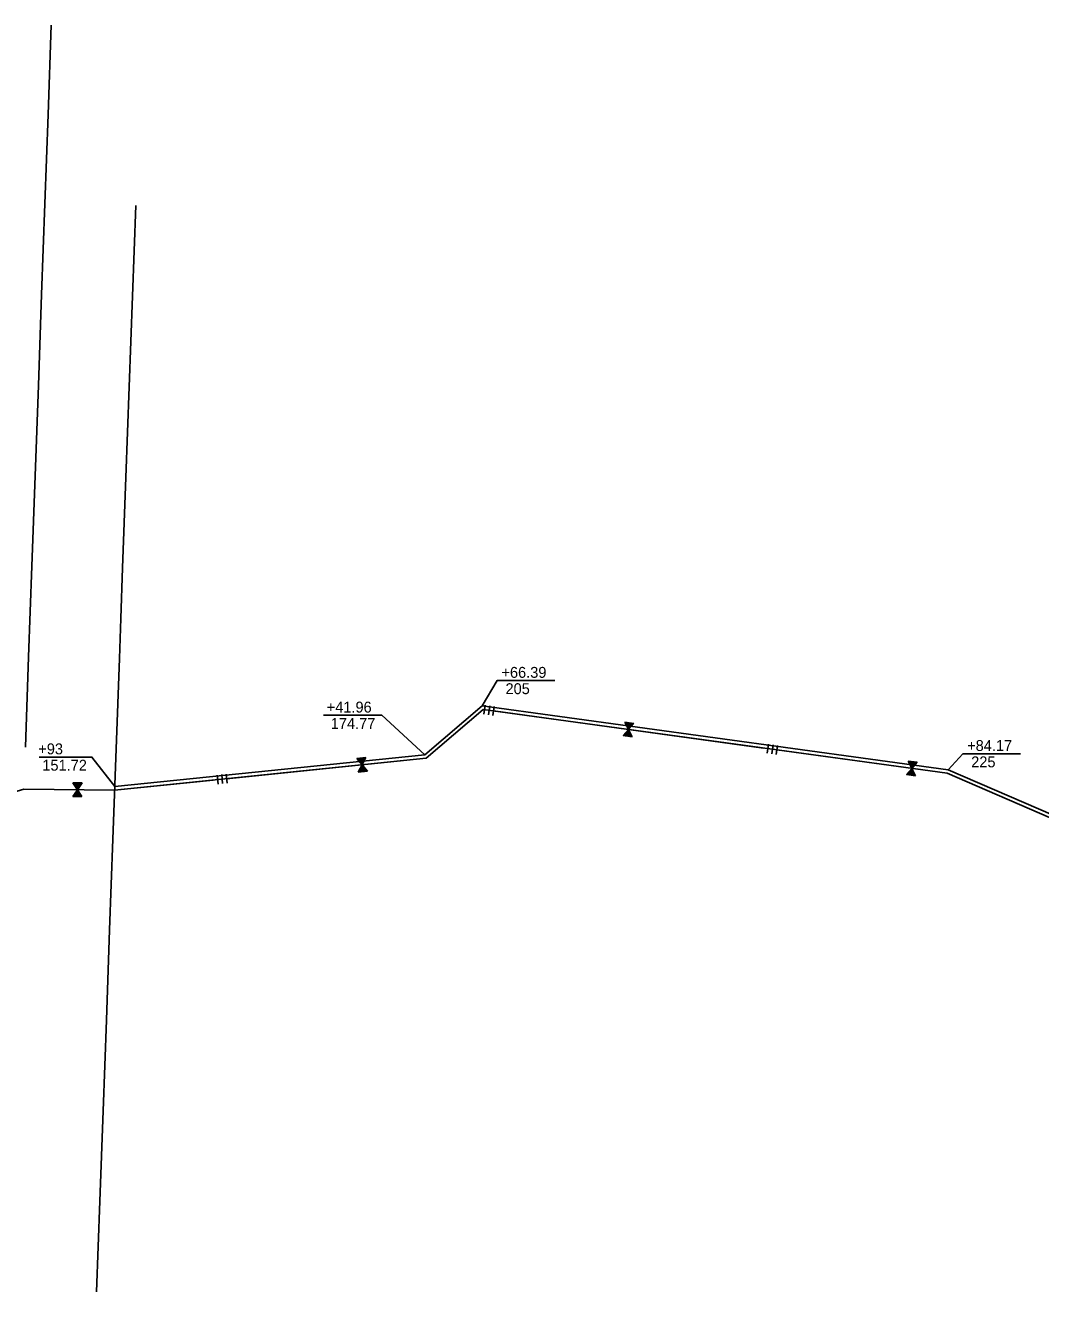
# Model space of a CAD drawing. Extents: x 979729 to 993523, y 1834148 to 1845433.
# Drawn here: x 991656 to 992215, y 1839507 to 1840205 of the extents above; entities that cross this region are included whole.
import ezdxf

# ---------------------------------------------------------------- set-up
doc = ezdxf.new("R2010")
doc.units = 0
for name, color, linetype in [('42', 7, 'Continuous'), ('51', 7, 'Continuous'), ('R_Draft', 7, 'Continuous'), ('S_EXIST_ROW', 7, 'Continuous')]:
    doc.layers.add(name, color=color, linetype=linetype)

msp = doc.modelspace()

# ---------------------------------------------------------------- linework, layer by layer
at = {"layer": '42'}
for p, q in [((991876.53, 1839801.26), (991907.89, 1839828.06)), ((991907.89, 1839828.06), (992163.34, 1839792.93)), ((991908.95, 1839830.44), (991908.27, 1839825.49)), ((991911.43, 1839830.1), (991910.75, 1839825.15)), ((991913.91, 1839829.76), (991913.23, 1839824.81)), ((991985.9, 1839821.12), (991987.87, 1839817.06)), ((991985.95, 1839821.06), (991985.99, 1839821.11)), ((991986.08, 1839820.83), (991986.29, 1839821.07)), ((991986.19, 1839820.57), (991986.59, 1839821.02)), ((991986.32, 1839820.34), (991986.89, 1839820.98)), ((991986.42, 1839820.08), (991987.19, 1839820.94)), ((991986.53, 1839819.83), (991987.48, 1839820.9)), ((991986.66, 1839819.6), (991987.78, 1839820.86)), ((991986.84, 1839819.42), (991987.97, 1839820.7)), ((991986.92, 1839819.13), (991988.38, 1839820.78)), ((991987.05, 1839818.9), (991988.67, 1839820.74)), ((991987.13, 1839818.62), (991988.97, 1839820.7)), ((991987.28, 1839818.41), (991989.27, 1839820.66)), ((991987.37, 1839818.13), (991989.57, 1839820.62)), ((991987.5, 1839817.91), (991989.86, 1839820.57)), ((991987.61, 1839817.65), (991990.16, 1839820.53)), ((991987.76, 1839817.44), (991990.46, 1839820.49)), ((991987.84, 1839817.16), (991990.76, 1839820.45)), ((991987.87, 1839817.06), (991990.86, 1839820.44)), ((991984.88, 1839813.69), (991987.87, 1839817.06)), ((991984.94, 1839813.74), (991984.97, 1839813.68)), ((991985.13, 1839813.92), (991985.27, 1839813.64)), ((991985.3, 1839814.14), (991985.57, 1839813.59)), ((991985.49, 1839814.32), (991985.87, 1839813.55)), ((991985.66, 1839814.55), (991986.16, 1839813.51)), ((991985.83, 1839814.77), (991986.46, 1839813.47)), ((991986.02, 1839814.95), (991986.76, 1839813.43)), ((991986.24, 1839815.08), (991986.98, 1839813.54)), ((991986.39, 1839815.33), (991987.35, 1839813.35)), ((991986.58, 1839815.52), (991987.65, 1839813.31)), ((991986.74, 1839815.76), (991987.95, 1839813.27)), ((991986.94, 1839815.92), (991988.25, 1839813.23)), ((991987.1, 1839816.17), (991988.55, 1839813.19)), ((991987.29, 1839816.35), (991988.84, 1839813.14)), ((991987.46, 1839816.57), (991989.14, 1839813.1)), ((991987.66, 1839816.73), (991989.44, 1839813.06)), ((991987.82, 1839816.98), (991989.73, 1839813.02)), ((991987.87, 1839817.06), (991989.83, 1839813.01)), ((992064.99, 1839808.98), (992064.3, 1839804.03)), ((992067.46, 1839808.64), (992066.78, 1839803.69)), ((992069.94, 1839808.3), (992069.26, 1839803.35)), ((991704.92, 1839783.66), (991876.53, 1839801.26)), ((991838.33, 1839801.11), (991841.2, 1839797.63)), ((991838.4, 1839801.06), (991838.43, 1839801.12)), ((991838.58, 1839800.87), (991838.72, 1839801.15)), ((991838.74, 1839800.64), (991839.02, 1839801.18)), ((991838.92, 1839800.45), (991839.32, 1839801.21)), ((991839.09, 1839800.23), (991839.62, 1839801.24)), ((991839.1, 1839793.65), (991841.2, 1839797.63)), ((991839.25, 1839800), (991839.92, 1839801.27)), ((991839.43, 1839799.81), (991840.22, 1839801.3)), ((991839.64, 1839799.67), (991840.44, 1839801.19)), ((991839.79, 1839799.42), (991840.82, 1839801.36)), ((991839.97, 1839799.23), (991841.12, 1839801.39)), ((991840.12, 1839798.97), (991841.41, 1839801.42)), ((991840.32, 1839798.81), (991841.71, 1839801.46)), ((991840.47, 1839798.56), (991842.01, 1839801.49)), ((991840.65, 1839798.37), (991842.31, 1839801.52)), ((991840.81, 1839798.14), (991842.61, 1839801.55)), ((991840.92, 1839797.06), (991843.37, 1839794.09)), ((991841, 1839797.97), (991842.91, 1839801.58)), ((991841.08, 1839797.26), (991843.67, 1839794.12)), ((991841.16, 1839797.72), (991843.21, 1839801.61)), ((991841.17, 1839797.54), (991843.97, 1839794.15)), ((991841.2, 1839797.63), (991843.31, 1839801.62)), ((991841.2, 1839797.63), (991844.07, 1839794.16)), ((992141.93, 1839799.66), (992143.9, 1839795.61)), ((992141.98, 1839799.6), (992142.03, 1839799.65)), ((992142.11, 1839799.37), (992142.32, 1839799.61)), ((992142.22, 1839799.11), (992142.62, 1839799.57)), ((992142.35, 1839798.88), (992142.92, 1839799.53)), ((992142.46, 1839798.63), (992143.22, 1839799.48)), ((992142.56, 1839798.37), (992143.51, 1839799.44)), ((992142.69, 1839798.14), (992143.81, 1839799.4)), ((992142.87, 1839797.96), (992144, 1839799.24)), ((992142.95, 1839797.67), (992144.41, 1839799.32)), ((992143.08, 1839797.44), (992144.71, 1839799.28)), ((992143.16, 1839797.16), (992145, 1839799.24)), ((992143.32, 1839796.96), (992145.3, 1839799.2)), ((992143.4, 1839796.68), (992145.6, 1839799.16)), ((992143.53, 1839796.45), (992145.9, 1839799.12)), ((992143.64, 1839796.19), (992146.19, 1839799.08)), ((992143.79, 1839795.98), (992146.49, 1839799.03)), ((992143.87, 1839795.7), (992146.79, 1839798.99)), ((992143.9, 1839795.61), (992146.89, 1839798.98)), ((991761.36, 1839791.96), (991761.87, 1839786.99)), ((991763.85, 1839792.21), (991764.36, 1839787.24)), ((991766.34, 1839792.47), (991766.85, 1839787.5)), ((991839.15, 1839793.71), (991839.19, 1839793.66)), ((991839.29, 1839793.93), (991839.49, 1839793.69)), ((991839.4, 1839794.19), (991839.79, 1839793.72)), ((991839.54, 1839794.41), (991840.09, 1839793.75)), ((991839.66, 1839794.67), (991840.39, 1839793.78)), ((991839.77, 1839794.92), (991840.69, 1839793.81)), ((991839.91, 1839795.14), (991840.98, 1839793.84)), ((991840.09, 1839795.32), (991841.18, 1839794)), ((991840.18, 1839795.6), (991841.58, 1839793.9)), ((991840.32, 1839795.82), (991841.88, 1839793.93)), ((991840.41, 1839796.1), (991842.18, 1839793.96)), ((991840.57, 1839796.3), (991842.48, 1839793.99)), ((991840.67, 1839796.58), (991842.78, 1839794.03)), ((991840.81, 1839796.8), (991843.08, 1839794.06)), ((992140.91, 1839792.23), (992143.9, 1839795.61)), ((992140.98, 1839792.28), (992141, 1839792.22)), ((992141.16, 1839792.46), (992141.3, 1839792.18)), ((992141.33, 1839792.68), (992141.6, 1839792.14)), ((992141.52, 1839792.87), (992141.9, 1839792.1)), ((992141.69, 1839793.09), (992142.19, 1839792.05)), ((992141.87, 1839793.31), (992142.49, 1839792.01)), ((992142.05, 1839793.49), (992142.79, 1839791.97)), ((992142.27, 1839793.62), (992143.02, 1839792.08)), ((992142.42, 1839793.87), (992143.39, 1839791.89)), ((992142.61, 1839794.06), (992143.68, 1839791.85)), ((992142.77, 1839794.3), (992143.98, 1839791.81)), ((992142.97, 1839794.46), (992144.28, 1839791.77)), ((992143.13, 1839794.71), (992144.58, 1839791.73)), ((992143.32, 1839794.89), (992144.87, 1839791.69)), ((992143.49, 1839795.11), (992145.17, 1839791.65)), ((992143.69, 1839795.27), (992145.47, 1839791.6)), ((992143.85, 1839795.52), (992145.77, 1839791.56)), ((992143.9, 1839795.61), (992145.87, 1839791.55)), ((992163.34, 1839792.93), (992363.33, 1839706.58)), ((991654.91, 1839784.25), (991704.92, 1839783.66)), ((991681.87, 1839780.18), (991684.42, 1839783.9)), ((991681.96, 1839787.68), (991684.42, 1839783.9)), ((991682.02, 1839787.63), (991682.06, 1839787.68)), ((991682.18, 1839787.42), (991682.36, 1839787.68)), ((991682.31, 1839787.17), (991682.66, 1839787.67)), ((991682.47, 1839786.96), (991682.96, 1839787.67)), ((991682.61, 1839786.72), (991683.26, 1839787.67)), ((991682.75, 1839786.48), (991683.56, 1839787.66)), ((991682.91, 1839786.26), (991683.86, 1839787.66)), ((991683.1, 1839786.11), (991684.07, 1839787.52)), ((991683.22, 1839785.83), (991684.46, 1839787.65)), ((991683.38, 1839785.62), (991684.76, 1839787.65)), ((991683.5, 1839785.36), (991685.06, 1839787.64)), ((991683.67, 1839785.17), (991685.36, 1839787.64)), ((991683.77, 1839782.92), (991685.57, 1839780.14)), ((991683.79, 1839784.9), (991685.66, 1839787.64)), ((991683.93, 1839783.12), (991685.87, 1839780.13)), ((991683.95, 1839784.69), (991685.96, 1839787.63)), ((991684.07, 1839783.36), (991686.17, 1839780.13)), ((991684.09, 1839784.45), (991686.26, 1839787.63)), ((991684.25, 1839783.55), (991686.47, 1839780.13)), ((991684.26, 1839784.26), (991686.56, 1839787.63)), ((991684.38, 1839783.99), (991686.86, 1839787.62)), ((991684.38, 1839783.81), (991686.77, 1839780.12)), ((991684.42, 1839783.9), (991686.96, 1839787.62)), ((991684.42, 1839783.9), (991686.87, 1839780.12)), ((991681.93, 1839780.24), (991681.97, 1839780.18)), ((991682.1, 1839780.44), (991682.27, 1839780.18)), ((991682.24, 1839780.68), (991682.57, 1839780.17)), ((991682.4, 1839780.89), (991682.87, 1839780.17)), ((991682.54, 1839781.13), (991683.17, 1839780.17)), ((991682.69, 1839781.37), (991683.47, 1839780.16)), ((991682.85, 1839781.58), (991683.77, 1839780.16)), ((991683.05, 1839781.73), (991683.98, 1839780.3)), ((991683.17, 1839782), (991684.37, 1839780.15)), ((991683.34, 1839782.2), (991684.67, 1839780.15)), ((991683.46, 1839782.47), (991684.97, 1839780.14)), ((991683.64, 1839782.65), (991685.27, 1839780.14))]:
    msp.add_line(p, q, dxfattribs=at)
for points in [[(991766.59, 1839789.98), (991876.53, 1839801.26), (991906.55, 1839826.91)], [(991913.57, 1839827.28), (992062.17, 1839806.85)], [(991985.9, 1839821.12), (991990.86, 1839820.44)], [(991984.88, 1839813.69), (991989.83, 1839813.01)], [(992069.6, 1839805.82), (992163.34, 1839792.93), (992214.18, 1839770.98)], [(991838.33, 1839801.11), (991843.31, 1839801.62)], [(992141.93, 1839799.66), (992146.89, 1839798.98)], [(991839.1, 1839793.65), (991844.07, 1839794.16)], [(992140.91, 1839792.23), (992145.87, 1839791.55)], [(991628.58, 1839776.26), (991654.91, 1839784.25), (991704.92, 1839783.66), (991759.13, 1839789.22)], [(991681.96, 1839787.68), (991686.96, 1839787.62)], [(991681.87, 1839780.18), (991686.87, 1839780.12)]]:
    msp.add_lwpolyline(points, dxfattribs=at)
at = {"layer": '51'}
for points in [[(991907.27, 1839830.17), (991875.71, 1839803.18), (991704.99, 1839785.68)], [(992163.88, 1839794.88), (991907.27, 1839830.17)], [(992364.23, 1839708.37), (992163.88, 1839794.88)]]:
    msp.add_lwpolyline(points, dxfattribs=at)
at = {"layer": 'R_Draft'}
for p, q in [((991921.53, 1839844.03), (991947.37, 1839844.03)), ((991819.93, 1839824.9), (991845.97, 1839824.9)), ((991663.32, 1839801.89), (991686.42, 1839801.89)), ((992177.98, 1839803.73), (992203.81, 1839803.73))]:
    msp.add_line(p, q, dxfattribs=at)
for points in [[(991907.27, 1839830.17), (991915.53, 1839844.03), (991921.53, 1839844.03)], [(991875.71, 1839803.18), (991851.97, 1839824.9), (991845.97, 1839824.9)], [(991704.99, 1839785.68), (991692.42, 1839801.89), (991686.42, 1839801.89)], [(992163.88, 1839794.88), (992171.98, 1839803.73), (992177.98, 1839803.73)]]:
    msp.add_lwpolyline(points, dxfattribs=at)
at = {"layer": 'S_EXIST_ROW'}
for p, q in [((991668.27, 1840155.74), (991670.04, 1840204.93)), ((991666.5, 1840106.55), (991668.27, 1840155.74)), ((991664.71, 1840056.59), (991666.5, 1840106.55)), ((991714.71, 1840055.7), (991716.5, 1840105.67)), ((991662.91, 1840006.62), (991664.71, 1840056.59)), ((991712.91, 1840005.73), (991714.71, 1840055.7)), ((991661.12, 1839956.8), (991662.91, 1840006.62)), ((991711.12, 1839955.9), (991712.91, 1840005.73)), ((991659.32, 1839906.98), (991661.12, 1839956.8)), ((991709.32, 1839906.07), (991711.12, 1839955.9)), ((991657.53, 1839857.17), (991659.32, 1839906.98)), ((991708.32, 1839878.22), (991709.32, 1839906.07)), ((991707.53, 1839856.23), (991708.32, 1839878.22)), ((991655.74, 1839807.35), (991657.53, 1839857.17)), ((991705.74, 1839806.4), (991707.53, 1839856.23)), ((991703.94, 1839756.57), (991705.74, 1839806.4)), ((991702.15, 1839706.74), (991703.94, 1839756.57)), ((991700.36, 1839656.91), (991702.15, 1839706.74)), ((991698.57, 1839607.07), (991700.36, 1839656.91)), ((991696.77, 1839557.24), (991698.57, 1839607.07)), ((991694.98, 1839507.41), (991696.77, 1839557.24))]:
    msp.add_line(p, q, dxfattribs=at)

# ---------------------------------------------------------------- texts
at = {"layer": 'R_Draft'}
for s, p in [('+66.39', (991917.91, 1839845.53)), (' 205', (991917.91, 1839836.53)), ('+41.96', (991821.7, 1839826.4)), (' 174.77', (991821.7, 1839817.4)), ('+84.17', (992174.35, 1839805.23)), ('+93', (991662.87, 1839803.39)), (' 151.72', (991662.87, 1839794.39)), (' 225', (992174.35, 1839796.23))]:
    msp.add_text(s, height=6, rotation=360, dxfattribs=at).set_placement(p)

doc.saveas('drawing.dxf')
